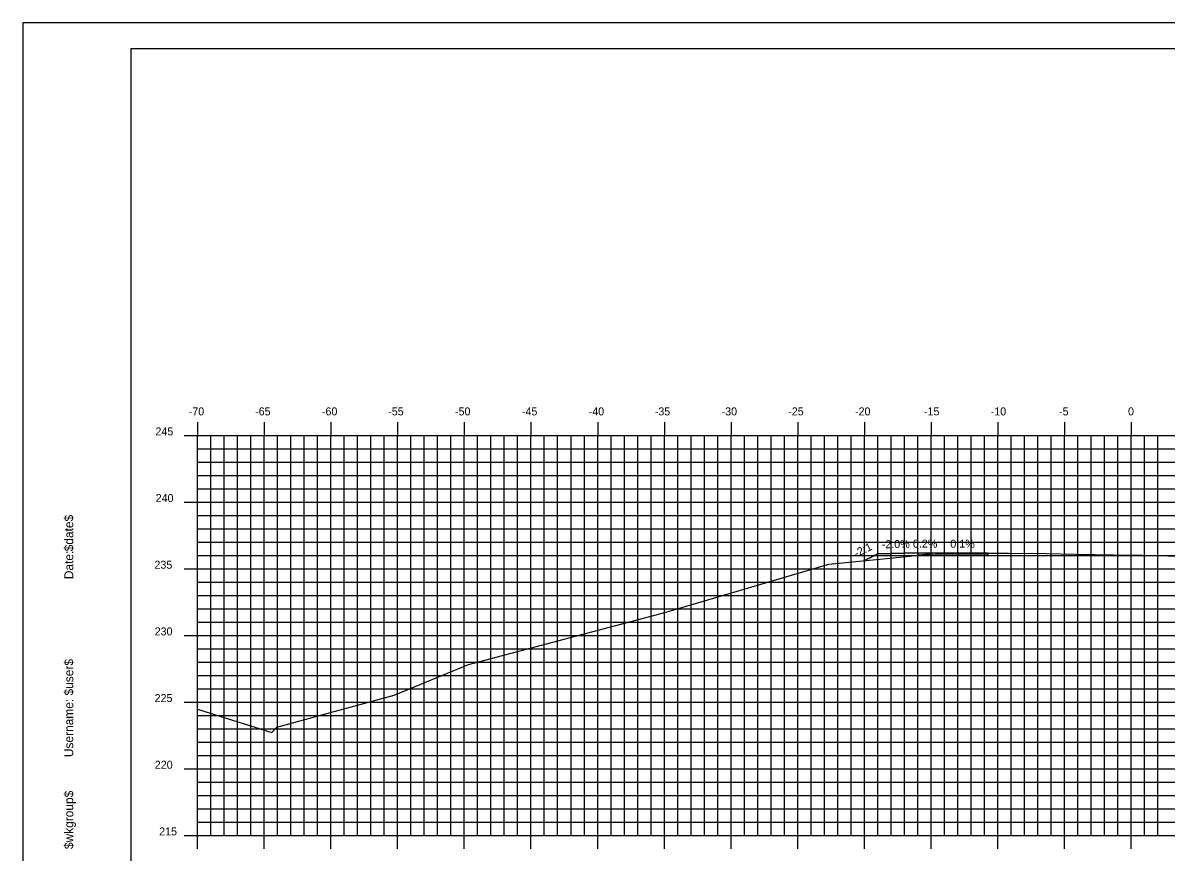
# Model space of a CAD drawing. Extents: x 1168600 to 1177589, y 610178 to 611246.
# Drawn here: x 1170888.9 to 1170974.6, y 610948.3 to 611010.5 of the extents above; entities that cross this region are included whole.
import ezdxf

# ---------------------------------------------------------------- set-up
doc = ezdxf.new("R2010")
doc.units = 0
for name, color, linetype in [('_Construction', 7, 'Continuous'), ('_Station Equation', 7, 'Continuous'), ('ANNOTATION', 7, 'Continuous'), ('D_Roadway_Edge_TW', 7, 'Continuous'), ('D_Slope_Direction', 7, 'Continuous'), ('D_Text_Standard', 7, 'Continuous'), ('H_V ANNOTATION', 7, 'Continuous'), ('MAJOR', 7, 'Continuous'), ('MATCH LINES', 7, 'Continuous'), ('MINOR', 7, 'Continuous')]:
    doc.layers.add(name, color=color, linetype=linetype)

msp = doc.modelspace()

# ---------------------------------------------------------------- linework, layer by layer
at = {"layer": '_Construction'}
for points in [[(1170888.926, 610900.537), (1171058.926, 610900.537), (1171058.926, 611010.537), (1170888.926, 611010.537)], [(1170897.019, 610903.596), (1171057.019, 610903.596), (1171057.019, 611008.596), (1170897.019, 611008.596)]]:
    msp.add_lwpolyline(points, close=True, dxfattribs=at)
at = {"layer": '_Station Equation'}
for points in [[(1170902.019, 610959.067), (1170907.579, 610957.317), (1170907.953, 610957.726), (1170908.968, 610957.985), (1170916.767, 610960.115), (1170922.325, 610962.411), (1170937.055, 610966.318), (1170949.353, 610969.929), (1170955.198, 610970.514), (1170957.314, 610970.777), (1170960.575, 610970.772), (1170962.829, 610970.769), (1170965.666, 610970.727), (1170967.829, 610970.692), (1170970.687, 610970.643), (1170972.829, 610970.605), (1170975.708, 610970.544)], [(1170902.019, 610959.067), (1170907.579, 610957.317), (1170907.953, 610957.726), (1170908.968, 610957.985), (1170916.767, 610960.115), (1170922.325, 610962.411), (1170937.056, 610966.318), (1170949.353, 610969.929), (1170955.198, 610970.514), (1170957.314, 610970.777), (1170960.574, 610970.772), (1170962.829, 610970.769), (1170965.667, 610970.727), (1170967.829, 610970.692), (1170970.688, 610970.643), (1170972.829, 610970.605), (1170975.709, 610970.544)]]:
    msp.add_lwpolyline(points, dxfattribs=at)
at = {"layer": 'D_Roadway_Edge_TW'}
msp.add_lwpolyline([(1170961.285, 610970.771), (1170957.314, 610970.776), (1170956.019, 610970.778), (1170956.019, 610970.653), (1170961.285, 610970.646), (1170961.285, 610970.771)], dxfattribs=at)
msp.add_lwpolyline([(1170961.285, 610970.771), (1170957.314, 610970.776), (1170956.019, 610970.778), (1170956.019, 610970.653), (1170961.285, 610970.646), (1170961.285, 610970.771)], dxfattribs=at)
at = {"layer": 'D_Slope_Direction'}
for points in [[(1170953.019, 610970.718), (1170951.963, 610970.19)], [(1170953.019, 610970.718), (1170951.963, 610970.19)], [(1170953.019, 610970.718), (1170951.963, 610970.19)], [(1170953.019, 610970.718), (1170951.963, 610970.19)], [(1170953.019, 610970.718), (1170951.963, 610970.19)], [(1170953.019, 610970.718), (1170951.963, 610970.19)], [(1170953.019, 610970.718), (1170951.963, 610970.19)], [(1170956.019, 610970.778), (1170953.019, 610970.718)], [(1170956.019, 610970.778), (1170953.019, 610970.718)]]:
    msp.add_lwpolyline(points, dxfattribs=at)
at = {"layer": 'D_Text_Standard'}
msp.add_lwpolyline([(1170951.963, 610970.19), (1170953.01, 610970.714), (1170953.019, 610970.718), (1170956.016, 610970.778), (1170956.019, 610970.778), (1170956.662, 610970.777), (1170957.315, 610970.776), (1170957.316, 610970.776), (1170961.286, 610970.771)], dxfattribs=at)
at = {"layer": 'MAJOR'}
for p, q in [((1170902.019, 610980.598), (1170902.019, 610979.596)), ((1170907.019, 610980.598), (1170907.019, 610979.596)), ((1170912.019, 610980.598), (1170912.019, 610979.596)), ((1170917.019, 610980.598), (1170917.019, 610979.596)), ((1170922.019, 610980.598), (1170922.019, 610979.596)), ((1170927.019, 610980.598), (1170927.019, 610979.596)), ((1170932.019, 610980.598), (1170932.019, 610979.596)), ((1170937.019, 610980.598), (1170937.019, 610979.596)), ((1170942.019, 610980.598), (1170942.019, 610979.596)), ((1170947.019, 610980.598), (1170947.019, 610979.596)), ((1170952.019, 610980.598), (1170952.019, 610979.596)), ((1170957.019, 610980.598), (1170957.019, 610979.596)), ((1170962.019, 610980.598), (1170962.019, 610979.596)), ((1170967.019, 610980.598), (1170967.019, 610979.596)), ((1170972.019, 610980.598), (1170972.019, 610979.596)), ((1170901.017, 610979.596), (1170902.019, 610979.596)), ((1170902.019, 610979.596), (1171042.019, 610979.596)), ((1170902.019, 610949.596), (1170902.019, 610979.596)), ((1170902.019, 610949.596), (1170902.019, 610979.596)), ((1170902.019, 610979.596), (1171042.019, 610979.596)), ((1170907.019, 610949.596), (1170907.019, 610979.596)), ((1170912.019, 610949.596), (1170912.019, 610979.596)), ((1170917.019, 610949.596), (1170917.019, 610979.596)), ((1170922.019, 610949.596), (1170922.019, 610979.596)), ((1170927.019, 610949.596), (1170927.019, 610979.596)), ((1170932.019, 610949.596), (1170932.019, 610979.596)), ((1170937.019, 610949.596), (1170937.019, 610979.596)), ((1170942.019, 610949.596), (1170942.019, 610979.596)), ((1170947.019, 610949.596), (1170947.019, 610979.596)), ((1170952.019, 610949.596), (1170952.019, 610979.596)), ((1170957.019, 610949.596), (1170957.019, 610979.596)), ((1170962.019, 610949.596), (1170962.019, 610979.596)), ((1170967.019, 610949.596), (1170967.019, 610979.596)), ((1170972.019, 610949.596), (1170972.019, 610979.596)), ((1170901.017, 610974.596), (1170902.019, 610974.596)), ((1170902.019, 610974.596), (1171042.019, 610974.596)), ((1170901.017, 610969.596), (1170902.019, 610969.596)), ((1170902.019, 610969.596), (1171042.019, 610969.596)), ((1170901.017, 610964.596), (1170902.019, 610964.596)), ((1170902.019, 610964.596), (1171042.019, 610964.596)), ((1170901.017, 610959.596), (1170902.019, 610959.596)), ((1170902.019, 610959.596), (1171042.019, 610959.596)), ((1170901.017, 610954.596), (1170902.019, 610954.596)), ((1170902.019, 610954.596), (1171042.019, 610954.596)), ((1170901.017, 610949.596), (1170902.019, 610949.596)), ((1170902.019, 610949.596), (1171042.019, 610949.596)), ((1170902.019, 610949.596), (1171042.019, 610949.596)), ((1170902.019, 610948.594), (1170902.019, 610949.596)), ((1170907.019, 610948.594), (1170907.019, 610949.596)), ((1170912.019, 610948.594), (1170912.019, 610949.596)), ((1170917.019, 610948.594), (1170917.019, 610949.596)), ((1170922.019, 610948.594), (1170922.019, 610949.596)), ((1170927.019, 610948.594), (1170927.019, 610949.596)), ((1170932.019, 610948.594), (1170932.019, 610949.596)), ((1170937.019, 610948.594), (1170937.019, 610949.596)), ((1170942.019, 610948.594), (1170942.019, 610949.596)), ((1170947.019, 610948.594), (1170947.019, 610949.596)), ((1170952.019, 610948.594), (1170952.019, 610949.596)), ((1170957.019, 610948.594), (1170957.019, 610949.596)), ((1170962.019, 610948.594), (1170962.019, 610949.596)), ((1170967.019, 610948.594), (1170967.019, 610949.596)), ((1170972.019, 610948.594), (1170972.019, 610949.596))]:
    msp.add_line(p, q, dxfattribs=at)
at = {"layer": 'MATCH LINES'}
msp.add_lwpolyline([(1170956.019, 610970.778), (1170956.019, 610970.653)], dxfattribs=at)
msp.add_lwpolyline([(1170956.019, 610970.778), (1170956.019, 610970.653)], dxfattribs=at)
at = {"layer": 'MINOR'}
for p, q in [((1170903.019, 610949.596), (1170903.019, 610979.596)), ((1170904.019, 610949.596), (1170904.019, 610979.596)), ((1170905.019, 610949.596), (1170905.019, 610979.596)), ((1170906.019, 610949.596), (1170906.019, 610979.596)), ((1170908.019, 610949.596), (1170908.019, 610979.596)), ((1170909.019, 610949.596), (1170909.019, 610979.596)), ((1170910.019, 610949.596), (1170910.019, 610979.596)), ((1170911.019, 610949.596), (1170911.019, 610979.596)), ((1170913.019, 610949.596), (1170913.019, 610979.596)), ((1170914.019, 610949.596), (1170914.019, 610979.596)), ((1170915.019, 610949.596), (1170915.019, 610979.596)), ((1170916.019, 610949.596), (1170916.019, 610979.596)), ((1170918.019, 610949.596), (1170918.019, 610979.596)), ((1170919.019, 610949.596), (1170919.019, 610979.596)), ((1170920.019, 610949.596), (1170920.019, 610979.596)), ((1170921.019, 610949.596), (1170921.019, 610979.596)), ((1170923.019, 610949.596), (1170923.019, 610979.596)), ((1170924.019, 610949.596), (1170924.019, 610979.596)), ((1170925.019, 610949.596), (1170925.019, 610979.596)), ((1170926.019, 610949.596), (1170926.019, 610979.596)), ((1170928.019, 610949.596), (1170928.019, 610979.596)), ((1170929.019, 610949.596), (1170929.019, 610979.596)), ((1170930.019, 610949.596), (1170930.019, 610979.596)), ((1170931.019, 610949.596), (1170931.019, 610979.596)), ((1170933.019, 610949.596), (1170933.019, 610979.596)), ((1170934.019, 610949.596), (1170934.019, 610979.596)), ((1170935.019, 610949.596), (1170935.019, 610979.596)), ((1170936.019, 610949.596), (1170936.019, 610979.596)), ((1170938.019, 610949.596), (1170938.019, 610979.596)), ((1170939.019, 610949.596), (1170939.019, 610979.596)), ((1170940.019, 610949.596), (1170940.019, 610979.596)), ((1170941.019, 610949.596), (1170941.019, 610979.596)), ((1170943.019, 610949.596), (1170943.019, 610979.596)), ((1170944.019, 610949.596), (1170944.019, 610979.596)), ((1170945.019, 610949.596), (1170945.019, 610979.596)), ((1170946.019, 610949.596), (1170946.019, 610979.596)), ((1170948.019, 610949.596), (1170948.019, 610979.596)), ((1170949.019, 610949.596), (1170949.019, 610979.596)), ((1170950.019, 610949.596), (1170950.019, 610979.596)), ((1170951.019, 610949.596), (1170951.019, 610979.596)), ((1170953.019, 610949.596), (1170953.019, 610979.596)), ((1170954.019, 610949.596), (1170954.019, 610979.596)), ((1170955.019, 610949.596), (1170955.019, 610979.596)), ((1170956.019, 610949.596), (1170956.019, 610979.596)), ((1170958.019, 610949.596), (1170958.019, 610979.596)), ((1170959.019, 610949.596), (1170959.019, 610979.596)), ((1170960.019, 610949.596), (1170960.019, 610979.596)), ((1170961.019, 610949.596), (1170961.019, 610979.596)), ((1170963.019, 610949.596), (1170963.019, 610979.596)), ((1170964.019, 610949.596), (1170964.019, 610979.596)), ((1170965.019, 610949.596), (1170965.019, 610979.596)), ((1170966.019, 610949.596), (1170966.019, 610979.596)), ((1170968.019, 610949.596), (1170968.019, 610979.596)), ((1170969.019, 610949.596), (1170969.019, 610979.596)), ((1170970.019, 610949.596), (1170970.019, 610979.596)), ((1170971.019, 610949.596), (1170971.019, 610979.596)), ((1170973.019, 610949.596), (1170973.019, 610979.596)), ((1170974.019, 610949.596), (1170974.019, 610979.596)), ((1170902.019, 610978.596), (1171042.019, 610978.596)), ((1170902.019, 610978.596), (1170903.021, 610978.596)), ((1170902.019, 610977.596), (1171042.019, 610977.596)), ((1170902.019, 610977.596), (1170903.021, 610977.596)), ((1170902.019, 610976.596), (1171042.019, 610976.596)), ((1170902.019, 610976.596), (1170903.021, 610976.596)), ((1170902.019, 610975.596), (1171042.019, 610975.596)), ((1170902.019, 610975.596), (1170903.021, 610975.596)), ((1170902.019, 610973.596), (1171042.019, 610973.596)), ((1170902.019, 610973.596), (1170903.021, 610973.596)), ((1170902.019, 610972.596), (1171042.019, 610972.596)), ((1170902.019, 610972.596), (1170903.021, 610972.596)), ((1170902.019, 610971.596), (1171042.019, 610971.596)), ((1170902.019, 610971.596), (1170903.021, 610971.596)), ((1170902.019, 610970.596), (1171042.019, 610970.596)), ((1170902.019, 610970.596), (1170903.021, 610970.596)), ((1170902.019, 610968.596), (1171042.019, 610968.596)), ((1170902.019, 610968.596), (1170903.021, 610968.596)), ((1170902.019, 610967.596), (1171042.019, 610967.596)), ((1170902.019, 610967.596), (1170903.021, 610967.596)), ((1170902.019, 610966.596), (1171042.019, 610966.596)), ((1170902.019, 610966.596), (1170903.021, 610966.596)), ((1170902.019, 610965.596), (1171042.019, 610965.596)), ((1170902.019, 610965.596), (1170903.021, 610965.596)), ((1170902.019, 610963.596), (1171042.019, 610963.596)), ((1170902.019, 610963.596), (1170903.021, 610963.596)), ((1170902.019, 610962.596), (1171042.019, 610962.596)), ((1170902.019, 610962.596), (1170903.021, 610962.596)), ((1170902.019, 610961.596), (1171042.019, 610961.596)), ((1170902.019, 610961.596), (1170903.021, 610961.596)), ((1170902.019, 610960.596), (1171042.019, 610960.596)), ((1170902.019, 610960.596), (1170903.021, 610960.596)), ((1170902.019, 610958.596), (1171042.019, 610958.596)), ((1170902.019, 610958.596), (1170903.021, 610958.596)), ((1170902.019, 610957.596), (1171042.019, 610957.596)), ((1170902.019, 610957.596), (1170903.021, 610957.596)), ((1170902.019, 610956.596), (1171042.019, 610956.596)), ((1170902.019, 610956.596), (1170903.021, 610956.596)), ((1170902.019, 610955.596), (1171042.019, 610955.596)), ((1170902.019, 610955.596), (1170903.021, 610955.596)), ((1170902.019, 610953.596), (1171042.019, 610953.596)), ((1170902.019, 610953.596), (1170903.021, 610953.596)), ((1170902.019, 610952.596), (1171042.019, 610952.596)), ((1170902.019, 610952.596), (1170903.021, 610952.596)), ((1170902.019, 610951.596), (1171042.019, 610951.596)), ((1170902.019, 610951.596), (1170903.021, 610951.596)), ((1170902.019, 610950.596), (1171042.019, 610950.596)), ((1170902.019, 610950.596), (1170903.021, 610950.596))]:
    msp.add_line(p, q, dxfattribs=at)

# ---------------------------------------------------------------- texts
at = {"layer": '_Construction'}
for s, p in [('$date$', (1170892.704, 610970.901)), ('Date:', (1170892.704, 610968.813)), ('$user$', (1170892.704, 610960.088)), ('Username:', (1170892.704, 610955.464)), ('$wkgroup$', (1170892.704, 610948.566))]:
    msp.add_text(s, height=0.6696, rotation=90, dxfattribs=at).set_placement(p)
at = {"layer": 'ANNOTATION'}
for s, rotation, p in [('-2:1', 26.55275, (1170951.416, 610970.435)), ('-2.0%', 1.14436, (1170953.321, 610971.125)), ('0.2%', 359.91154, (1170955.652, 610971.179)), ('0.1%', 359.92661, (1170958.457, 610971.175))]:
    msp.add_text(s, height=0.6, rotation=rotation, dxfattribs=at).set_placement(p)
at = {"layer": 'H_V ANNOTATION'}
for s, p in [('-70', (1170901.361, 610981.096)), ('-65', (1170906.337, 610981.096)), ('-60', (1170911.345, 610981.096)), ('-55', (1170916.315, 610981.096)), ('-50', (1170921.323, 610981.096)), ('-45', (1170926.337, 610981.096)), ('-40', (1170931.345, 610981.096)), ('-35', (1170936.299, 610981.096)), ('-30', (1170941.307, 610981.096)), ('-25', (1170946.304, 610981.096)), ('-20', (1170951.312, 610981.096)), ('-15', (1170956.476, 610981.096)), ('-10', (1170961.484, 610981.096)), ('-5', (1170966.609, 610981.096)), ('0', (1170971.778, 610981.096)), ('245', (1170898.865, 610979.596)), ('240', (1170898.881, 610974.596)), ('235', (1170898.79, 610969.596)), ('230', (1170898.806, 610964.596)), ('225', (1170898.801, 610959.596)), ('220', (1170898.817, 610954.596)), ('215', (1170899.143, 610949.596))]:
    msp.add_text(s, height=0.6, dxfattribs=at).set_placement(p)

doc.saveas('drawing.dxf')
